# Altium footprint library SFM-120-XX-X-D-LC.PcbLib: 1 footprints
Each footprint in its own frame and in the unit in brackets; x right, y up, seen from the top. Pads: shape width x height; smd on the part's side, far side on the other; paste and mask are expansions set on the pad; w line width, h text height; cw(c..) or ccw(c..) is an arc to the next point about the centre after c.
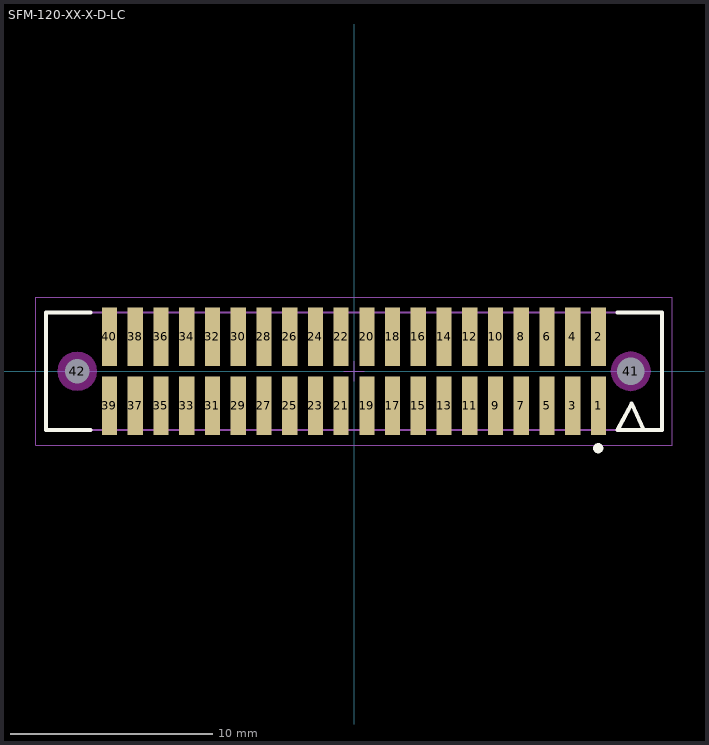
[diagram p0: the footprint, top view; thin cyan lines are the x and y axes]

## SFM-120-XX-X-D-LC [mm] "1.27mm pitch, 40 pin, micro socket strip; SMT"
height 4.57
pads (42):
  rect 0.75x2.9 smd mask+0: 1(12.065,-1.7) 2(12.065,1.7) 3(10.795,-1.7) 4(10.795,1.7) 5(9.525,-1.7) 6(9.525,1.7) 7(8.255,-1.7) 8(8.255,1.7) 9(6.985,-1.7) 10(6.985,1.7) 11(5.715,-1.7) 12(5.715,1.7) 13(4.445,-1.7) 14(4.445,1.7) 15(3.175,-1.7) 16(3.175,1.7) 17(1.905,-1.7) 18(1.905,1.7) 19(0.635,-1.7) 20(0.635,1.7) 21(-0.635,-1.7) 22(-0.635,1.7) 23(-1.905,-1.7) 24(-1.905,1.7) 25(-3.175,-1.7) 26(-3.175,1.7) 27(-4.445,-1.7) 28(-4.445,1.7) 29(-5.715,-1.7) 30(-5.715,1.7) 31(-6.985,-1.7) 32(-6.985,1.7) 33(-8.255,-1.7) 34(-8.255,1.7) 35(-9.525,-1.7) 36(-9.525,1.7) 37(-10.795,-1.7) 38(-10.795,1.7) 39(-12.065,-1.7) 40(-12.065,1.7)
  round 1 hole 1.35 unplated mask+0: 41(13.65,0)
  round 1 hole 1.2 unplated mask+0: 42(-13.65,0)
Top Overlay:
  circle w0.25: c12.05,-3.8 r0.125
  lines w0.2: -13,-2.9 -15.2,-2.9 -15.2,2.9 -13,2.9 ; 13,2.9 15.2,2.9 15.2,-2.9 13,-2.9 13.7,-1.6 14.3,-2.9
Keep-Out Layer:
  pour cut-out: -12.685,0 -12.718,0.251 -12.815,0.485 -12.97,0.686 -13.17,0.84 -13.405,0.937 -13.656,0.97 -13.907,0.937 -14.141,0.84 -14.342,0.686 -14.496,0.485 -14.593,0.251 -14.626,0 -14.593,-0.251 -14.496,-0.485 -14.342,-0.686 -14.141,-0.84 -13.907,-0.937 -13.656,-0.97 -13.405,-0.937 -13.17,-0.84 -12.97,-0.686 -12.815,-0.485 -12.718,-0.251
  pour cut-out: 14.632,0 14.599,0.253 14.502,0.488 14.346,0.691 14.144,0.846 13.908,0.943 13.656,0.977 13.403,0.943 13.167,0.846 12.965,0.691 12.81,0.488 12.712,0.253 12.679,0 12.712,-0.253 12.81,-0.488 12.965,-0.691 13.167,-0.846 13.403,-0.943 13.656,-0.977 13.908,-0.943 14.144,-0.846 14.346,-0.691 14.502,-0.488 14.599,-0.253
Mechanical 12:
  lines w0.001: -15.2,-2.9 15.2,-2.9 15.2,2.9 -15.2,2.9 -15.2,-2.9
Mechanical 13:
  circle w0.1: c12.05,-3.8 r0.125
  lines w0.1: 13,-2.9 13.7,-1.6 14.3,-2.9 ; -15.2,-2.9 15.2,-2.9 15.2,2.9 -15.2,2.9 -15.2,-2.9
  text ".Designator" at 0,-0.127 h1.52
Mechanical 15:
  lines w0.05: -0.5,0 0.5,0 ; 0,-0.5 0,0.5 ; -15.7,-3.65 15.7,-3.65 15.7,3.65 -15.7,3.65 -15.7,-3.65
